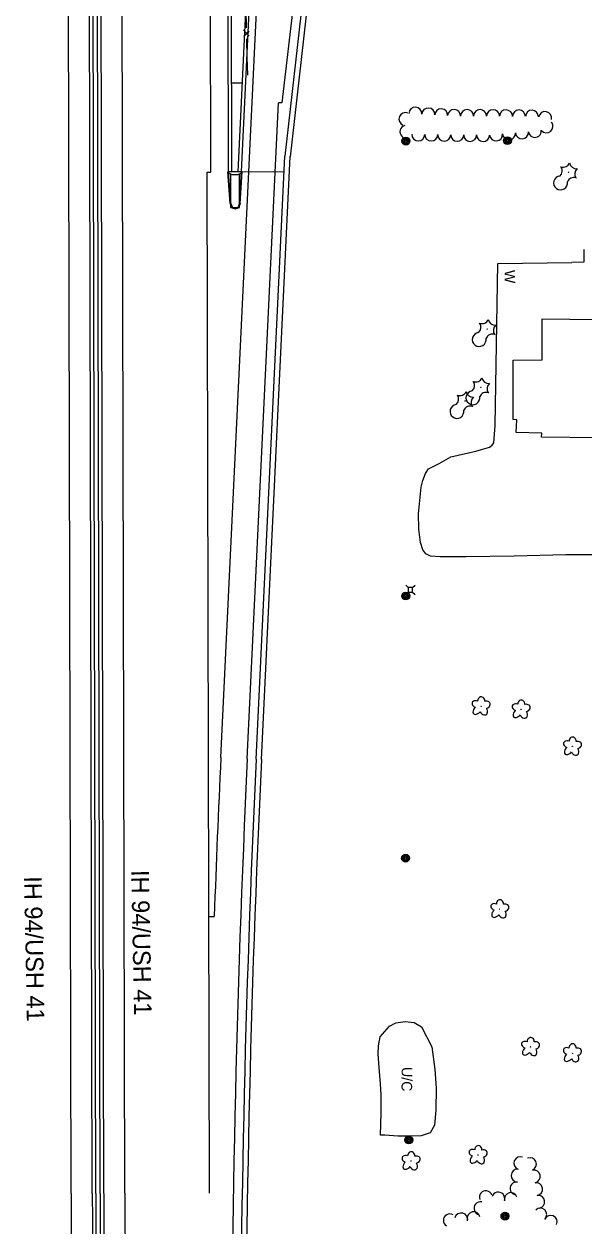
# Model space of a CAD drawing. Extents: x 588843 to 2552415, y 180129 to 269402.
# Drawn here: x 593977 to 594294, y 183685 to 184366 of the extents above; entities that cross this region are included whole.
import ezdxf

# ---------------------------------------------------------------- set-up
doc = ezdxf.new("R2010")
doc.units = 0
for name, color, linetype in [('Default', 7, 'Continuous'), ('E_AREA', 7, 'Continuous'), ('E_AREA_Text', 7, 'Continuous'), ('E_BLD', 7, 'Continuous'), ('E_DWY', 7, 'Continuous'), ('E_FEN_P', 7, 'Continuous'), ('E_LAND_TreeLine_P', 7, 'Continuous'), ('E_LAND_Vegetation', 7, 'Continuous'), ('E_MISCPROP', 7, 'Continuous'), ('E_RDWY_Text', 7, 'Continuous'), ('E_UTL_AG_Bold', 7, 'Continuous'), ('E_WAL', 7, 'Continuous'), ('E_WAL_Text', 7, 'Continuous'), ('P_BMGRD', 7, 'Continuous'), ('P_RDWY_BarrierConc', 7, 'Continuous'), ('P_RDWY_PavtEdge', 7, 'Continuous'), ('P_RDWY_ShldAgg', 7, 'Continuous'), ('P_RDWY_ShldPaved', 7, 'Continuous')]:
    doc.layers.add(name, color=color, linetype=linetype)

# ---------------------------------------------------------------- blocks, each defined once
blk = doc.blocks.new('POLE')
at = {"layer": 'Default'}
for radius in [4.46, 3.35, 2.23, 1.12]:
    blk.add_circle((0, 0), radius, dxfattribs=at)
blk = doc.blocks.new('PED')
at = {"layer": 'Default'}
for p, q in [((-2.5, 2.5), (-5.3, 5.3)), ((2.5, 2.5), (5.3, 5.3)), ((-2.5, -2.5), (-5.3, -5.3)), ((2.5, -2.5), (5.3, -5.3))]:
    blk.add_line(p, q, dxfattribs=at)
blk.add_lwpolyline([(-2.5, -2.5), (2.5, -2.5), (2.5, 2.5), (-2.5, 2.5)], close=True, dxfattribs=at)
blk = doc.blocks.new('UCA')
at = {"layer": 'E_AREA_Text'}
blk.add_text('U/C', height=12, dxfattribs=at).set_placement((-15.3, -6))
blk = doc.blocks.new('DTRE')
at = {"layer": 'Default'}
blk.add_circle((-0.2, 0), 0.183, dxfattribs=at)
for centre, major_axis, ratio in [((-5.9, 0.2), (4.93, -0.12), 0.832022), ((-1.9, 5.3), (1.36, -4.98), 0.782863), ((4.1, 2.7), (-5.27, -2.93), 0.691916), ((-2.5, -5.2), (1.8, 4.86), 0.716896), ((3.5, -3.7), (-5.01, 4.58), 0.560249)]:
    blk.add_ellipse(centre, major_axis=major_axis, ratio=ratio, start_param=1.570796, end_param=4.712389, dxfattribs=at)
blk = doc.blocks.new('CTRE')
at = {"layer": 'Default'}
blk.add_circle((0, 0), 0.223, dxfattribs=at)
for centre, start, end in [((-12, 9), 280.2067, 5.9716), ((-13.8, -5.9), 340.2113, 65.9762), ((1.8, 14.9), 220.2113, 305.9762), ((13.8, 5.9), 160.2113, 245.9762), ((-1.8, -14.9), 40.2113, 125.9762), ((12, -9), 185.9272, 100.2511)]:
    blk.add_arc(centre, 7.87, start, end, dxfattribs=at)
blk = doc.blocks.new('W_11')
at = {"layer": 'E_WAL_Text'}
blk.add_text('W', height=12, dxfattribs=at).set_placement((-4.5, -6))

msp = doc.modelspace()

# ---------------------------------------------------------------- linework, layer by layer
at = {"layer": 'E_AREA'}
msp.add_lwpolyline([(594179, 183736.21), (594179.31, 183748.87), (594179.35, 183759.08), (594178.94, 183765.22), (594178.26, 183774.48), (594177.67, 183782.14), (594177.82, 183786.94), (594178.82, 183791.86), (594184.06, 183798.03), (594187.73, 183799.82), (594192.94, 183800.57), (594198.13, 183800.14), (594202.27, 183797.69), (594208.02, 183786.37), (594209.8, 183773.5), (594210.47, 183763.02), (594210.37, 183750.41), (594209.51, 183741.88), (594207.06, 183737.45), (594202.1, 183735.85), (594195.5, 183735.6), (594188.82, 183735.65), (594181.34, 183736.09), (594179, 183736.21)], close=True, dxfattribs=at)
at = {"layer": 'E_BLD'}
msp.add_lwpolyline([(594335.03, 184131.39), (594270.25, 184132.15), (594270.4, 184134.44), (594255.97, 184134.67), (594256.3, 184141.97), (594254.13, 184142.03), (594254.23, 184175.78), (594270.74, 184175.88), (594270.63, 184199.23), (594317.46, 184198.7)], dxfattribs=at)
at = {"layer": 'E_DWY'}
for points in [[(594294.37, 184238.51), (594294.35, 184231.3), (594287.53, 184231.22)], [(594412.28, 184064.38), (594361.83, 184064.64), (594313.89, 184065.35), (594284.17, 184065.27), (594254.79, 184064.68), (594227.3, 184064.25), (594212.84, 184064.31), (594207.31, 184064.55), (594204.59, 184065.98), (594203.01, 184068.21), (594201.69, 184072.37), (594200.76, 184079.96), (594200.46, 184088.67), (594201.99, 184103.8), (594202.93, 184107.56), (594204.58, 184111.45), (594206.18, 184114.05), (594212.19, 184117.12), (594218.87, 184121.03), (594233.09, 184124.11), (594240.73, 184126.39), (594242.24, 184127.51), (594243.25, 184128.81), (594244.03, 184138.73)]]:
    msp.add_lwpolyline(points, dxfattribs=at)
at = {"layer": 'E_FEN_P'}
for p, q in [((594104.55, 184359.61), (594101.35, 184363.11)), ((594101.43, 184359.7), (594104.42, 184362.46))]:
    msp.add_line(p, q, dxfattribs=at)
for points in [[(594103, 184364.35), (594102.76, 184374.62)], [(594103.39, 184347.72), (594103.15, 184357.99)], [(594103.64, 184337.45), (594103.39, 184347.72)]]:
    msp.add_lwpolyline(points, dxfattribs=at)
at = {"layer": 'E_LAND_TreeLine_P'}
for centre, radius, start, end in [((594198.69, 184315.55), 3.68, 356.7686, 176.7686), ((594193.11, 184312.54), 3.68, 67.76994, 247.76994), ((594206.04, 184315.13), 3.68, 356.7686, 176.7686), ((594213.38, 184314.72), 3.68, 356.7686, 176.7686), ((594220.73, 184314.31), 3.68, 356.7686, 176.7686), ((594228.09, 184314.23), 3.68, 359.80504, 179.80504), ((594235.44, 184314.2), 3.68, 359.80504, 179.80504), ((594242.8, 184314.18), 3.68, 359.80504, 179.80504), ((594250.16, 184314.1), 3.68, 359.20132, 179.20132), ((594257.51, 184314), 3.68, 359.20132, 179.20132), ((594264.87, 184313.9), 3.68, 359.20132, 179.20132), ((594272.37, 184313.12), 3.68, 348.23517, 168.23517), ((594193.69, 184305.29), 3.68, 103.61842, 283.61842), ((594266.5, 184305.82), 3.68, 187.86261, 7.86261), ((594273.12, 184308.44), 3.68, 220.16899, 40.16899), ((594200.4, 184303.84), 3.68, 179.45865, 359.45865), ((594207.76, 184303.77), 3.68, 179.45865, 359.45865), ((594215.11, 184303.7), 3.68, 179.41999, 359.41999), ((594222.47, 184303.63), 3.68, 179.41999, 359.41999), ((594229.83, 184303.55), 3.68, 179.41999, 359.41999), ((594237.19, 184303.48), 3.68, 179.41999, 359.41999), ((594244.53, 184303.78), 3.68, 184.74473, 4.74473), ((594251.86, 184304.39), 3.68, 184.74473, 4.74473), ((594259.19, 184305), 3.68, 184.74473, 4.74473), ((594258.29, 183720.3), 3.66, 69.13052, 249.13052), ((594263.77, 183719.75), 3.66, 292.71782, 112.71782), ((594256.71, 183713.25), 3.66, 87.77912, 267.77912), ((594265.97, 183712.8), 3.66, 281.40003, 101.40003), ((594256.11, 183705.97), 3.66, 81.04261, 261.04261), ((594267.26, 183705.6), 3.66, 279.43231, 99.43231), ((594238.7, 183700.97), 3.66, 19.97891, 199.97891), ((594245.75, 183700.25), 3.66, 342.22848, 162.22848), ((594252.86, 183699.94), 3.66, 15.80306, 195.80306), ((594268.46, 183698.37), 3.66, 278.87191, 98.87191), ((594224.71, 183688.4), 3.66, 345.97245, 165.97245), ((594231.82, 183689.06), 3.66, 13.68239, 193.68239), ((594235.67, 183694.73), 3.66, 79.04093, 259.04093), ((594269.6, 183691.14), 3.66, 315.66343, 135.66343), ((594218.27, 183687.86), 3.66, 58.7903, 238.7903), ((594275.5, 183687), 3.66, 336.09091, 156.09091)]:
    msp.add_arc(centre, radius, start, end, dxfattribs=at)
at = {"layer": 'E_WAL'}
msp.add_lwpolyline([(594244.03, 184138.73), (594245.47, 184230.64), (594287.53, 184231.22)], dxfattribs=at)
at = {"layer": 'P_BMGRD'}
for p, q in [((594092.74, 184282.51), (594092.4, 184282.51)), ((594093.71, 184264.56), (594092.4, 184282.51)), ((594094.03, 184264.59), (594092.72, 184282.51)), ((594093.92, 184281.42), (594093.96, 184262.41)), ((594094.69, 184281.05), (594094.69, 184281.05)), ((594098.99, 184264.6), (594100.22, 184282.53)), ((594099.07, 184262.42), (594099.03, 184281.43)), ((594099.31, 184264.57), (594100.54, 184282.53)), ((594100.54, 184282.53), (594100.21, 184282.53)), ((594093.71, 184264.56), (594094.49, 184262.62)), ((594094.03, 184264.59), (594094.8, 184262.67)), ((594098.99, 184264.6), (594098.23, 184262.68)), ((594099.31, 184264.57), (594098.54, 184262.63)), ((594093.96, 184262.41), (594099.07, 184262.42))]:
    msp.add_line(p, q, dxfattribs=at)
msp.add_lwpolyline([(594100.22, 184282.65), (594092.72, 184282.63), (594092.8, 184281.96), (594094.69, 184281.05), (594098.26, 184281.06), (594100.14, 184281.97)], close=True, dxfattribs=at)
for major_axis in [(-2.09, 0), (-1.77, 0)]:
    msp.add_ellipse((594096.51, 184262.94), major_axis=major_axis, ratio=0.620755, start_param=0.243094, end_param=2.898499, dxfattribs=at)
at = {"layer": 'P_RDWY_BarrierConc'}
for p, q in [((594015.52, 183703.15), (594011.71, 185400.89)), ((594017.52, 183703.15), (594013.71, 185400.03)), ((594020.02, 183703.16), (594016.21, 185398.95)), ((594022.02, 183703.16), (594018.21, 185398.08)), ((594098.22, 184282.65), (594107.7, 184482.31)), ((594100.22, 184282.65), (594109.7, 184482.21)), ((594092.72, 184282.63), (594092.4, 184426.97)), ((594094.72, 184282.64), (594094.4, 184426.97)), ((594100.22, 184282.65), (594092.72, 184282.63))]:
    msp.add_line(p, q, dxfattribs=at)
for radius in [171884.59, 171882.59, 171880.09, 171878.09]:
    msp.add_arc((765899.68, 184089.33), radius, 180.1287302, 180.4530652, dxfattribs=at)
at = {"layer": 'P_RDWY_PavtEdge'}
for p, q in [((594003.52, 183703.12), (593999.78, 185371.14)), ((594034.02, 183703.19), (594030.35, 185336.23)), ((594082.72, 184282.49), (594080.35, 185336.34)), ((594104.23, 184282.67), (594113.7, 184482.02)), ((594140.21, 184471.08), (594123.1, 184321.72)), ((594100.61, 184332.95), (594094.61, 184332.93)), ((594103.42, 183949.62), (594121.1, 184321.82)), ((594123.1, 184321.72), (594121.1, 184321.82)), ((594080.72, 184282.47), (594082.72, 184282.49)), ((594082.02, 183703.3), (594080.72, 184282.47)), ((594088.44, 183950.33), (594104.23, 184282.66)), ((594100.22, 184282.64), (594124.26, 184282.82)), ((594081.67, 183860.29), (594084.67, 183860.3))]:
    msp.add_line(p, q, dxfattribs=at)
for centre, radius, start, end in [((602094.41, 183570.03), 8015, 177.280358, 177.924558), ((602094.41, 183570.03), 8000, 177.280358, 180.181641), ((765899.68, 184089.33), 171896.59, 180.1287302, 180.4530652), ((765899.68, 184089.33), 171866.09, 180.1287302, 180.4530652)]:
    msp.add_arc(centre, radius, start, end, dxfattribs=at)
at = {"layer": 'P_RDWY_ShldAgg'}
for p, q in [((594148.17, 184470.33), (594127.65, 184291.1)), ((594111.41, 183949.24), (594127.66, 184291.3))]:
    msp.add_line(p, q, dxfattribs=at)
msp.add_arc((602094.41, 183570.03), 7992, 177.280358, 180.181641, dxfattribs=at)
at = {"layer": 'P_RDWY_ShldPaved'}
for p in [(594145.19, 184470.67), (594108.42, 183949.38)]:
    msp.add_line(p, (594124.67, 184291.45), dxfattribs=at)
msp.add_arc((602094.41, 183570.03), 7995, 177.280358, 180.181641, dxfattribs=at)

# ---------------------------------------------------------------- block references
at = {"layer": 'E_AREA_Text', "xscale": 0.5, "yscale": 0.5, "rotation": -90.44645755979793}
msp.add_blockref('UCA', (594193.93, 183767.17), dxfattribs=at)
at = {"layer": 'E_LAND_Vegetation', "yscale": 0.5}
for name, p, xscale, rotation in [('CTRE', (594285.6, 184282.31), 0.49999999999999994, -90.03098035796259), ('CTRE', (594239.47, 184193.51), 0.49999999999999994, -90.03098035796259), ('CTRE', (594235.88, 184160.44), 0.49999999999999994, -90.03098035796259), ('CTRE', (594226.84, 184152.68), 0.49999999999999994, -90.03098035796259), ('DTRE', (594235.99, 183979.39), 0.5, -90.44645755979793), ('DTRE', (594258.7, 183977.58), 0.5, -90.44645755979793), ('DTRE', (594287.82, 183956.58), 0.5, -90.44645755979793), ('DTRE', (594246.6, 183864.27), 0.5, -90.44645755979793), ('DTRE', (594264.03, 183786.16), 0.5, -90.44645755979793), ('DTRE', (594287.78, 183782.58), 0.5, -90.44645755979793), ('DTRE', (594196.28, 183721.37), 0.5, -90.44645755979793), ('DTRE', (594234.31, 183724.85), 0.5, -90.44645755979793)]:
    msp.add_blockref(name, p, dxfattribs=dict(at, xscale=xscale, rotation=rotation))
at = {"layer": 'E_MISCPROP', "yscale": 0.5}
for p, xscale, rotation in [((594193.38, 184300.04), 0.49999999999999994, -90.03098035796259), ((594250.96, 184300.26), 0.49999999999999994, -90.03098035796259), ((594193.29, 184042.02), 0.5, 89.75405178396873), ((594193.18, 183893.27), 0.5, 89.75405178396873), ((594195.03, 183733.42), 0.5, 89.75405178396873), ((594249.55, 183690.23), 0.5, 89.75405178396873)]:
    msp.add_blockref('POLE', p, dxfattribs=dict(at, xscale=xscale, rotation=rotation))
at = {"layer": 'E_UTL_AG_Bold', "xscale": 0.5, "yscale": 0.5, "rotation": 89.75405178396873}
msp.add_blockref('PED', (594195.93, 184045.51), dxfattribs=at)
at = {"layer": 'E_WAL_Text', "xscale": 0.49999999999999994, "yscale": 0.5000000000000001, "rotation": -89.630833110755}
msp.add_blockref('W_11', (594252.32, 184224.68), dxfattribs=at)

# ---------------------------------------------------------------- texts
at = {"layer": 'E_RDWY_Text'}
for p in [(594037.6, 183886.48), (593976.78, 183882.94)]:
    msp.add_text('IH 94/USH 41', height=10, rotation=271.14065, dxfattribs=at).set_placement(p)

doc.saveas('drawing.dxf')
